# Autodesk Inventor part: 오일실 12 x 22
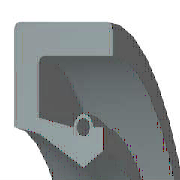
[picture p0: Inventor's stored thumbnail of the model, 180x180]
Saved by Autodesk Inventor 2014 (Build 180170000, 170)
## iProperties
IsCustomPart: 0
Created: 2015-10
Part Number: 오일실 12 x 22
Material: 고무
Description: 오일-실
Document SubType Name: Modeling
Standard: KS B 2804
Designer: mdu
Standards Organization: KS
Language: ko-KR
Size Designation: S - 12 22 7
Categories: <MemberInstance><Categories><Category DisplayName="샤프트 부품" InternalName="7f7aeb1f-a693-4053-b835-cee3144e0d98" Mnemonic="SHFT"><Category DisplayName="실링" Intern
Density: 0.93 g/cm^3
Appearance: 고무 - 검은색 - 버전 1.1
Author: mdu
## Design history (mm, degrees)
revolve "본체" stored, may be unused: angle "d17" = 90 deg
revolve "스프링1" stored, may be unused: angle "d18" = 90 deg
body "Solid1"
sketch "스케치1"
  geometry: L1 (0, 11)-(7, 11); L2 (7, 11)-(7, 9.75); L3 (7, 9.75)-(1.75, 9.75); L4 (0, 11)-(0, 8.1); L5 (0, 8.1)-(1.75, 7.75); L6 (1.75, 7.75)-(4.9, 6); L7 (4.9, 6)-(0, 6); L8 (6.3, 6.875)-(6.3, 8.1); L9 (0, 0)-(9.586, 0) reference; L10 (4.9, 6)-(6.3, 6.875); L11 (0, 18)-(0, -3) reference; L12 (-1.917, 0)-(11.503, 0) reference; L13 (4.2, 8.1)-(1.75, 8.59); L14 (1.75, 8.59)-(1.75, 9.75); L15 (6.3, 8.1)-(5.6, 8.1); C1 r 0.455 at (4.9, 8.1); A1 r 0.7 centre (4.9, 8.1) between (5.6, 8.1) and (4.2, 8.1)
  constraints: 26 end point, 5 horizontal alignment, 4 perpendicular, 2 centre point, 2 collinear, 2 horizontal, 2 parallel, 2 point on circle, 2 point on line, 2 vertical alignment, 1 coincident
  dimensions: "d0" = 22 diameter of L1 L9 (= SD2); "d1" = 13.75 diameter of L8.start L9 (= ABDM); "d2" = 1.25 distance of L1.end L2.end (computed from SD); "d3" = 0.91 diameter of C1 (= SPDI); "d4" = 1.4 diameter of A1 (= SPDA); "d5" = 12 diameter of L6.end L9 (= NND); "d6" = 15.5 diameter of L5.end L9 (= TKDM); "d7" = 16.2 diameter of L4.end L9 (= HLDM); "d8" = 4.9 distance from line of C1.centre L4 (= SPDST); "d9" = 6.3 distance between parallel lines of L8 L4 (= SDI); "d10" = 7 distance between parallel lines of L2 L4 (= SWDT); "d12" = 1.75 distance between parallel lines of L14 L4 (= SD)
fillet "모깎기1" dims "d11" = 0.3 (= RR)
other parameters: "SD2" = 22 [user parameter; used in 1 equation term], "SWDT" = 7 [user parameter; used in 1 equation term], "RR" = 0.3 [user parameter; used in 1 equation term], "SD" = 1.75 [user parameter; used in 2 equation terms], "NND" = 12 [user parameter; used in 1 equation term], "SPDA" = 1.4 [user parameter; used in 1 equation term], "SPDI" = 0.91 [user parameter; used in 1 equation term], "TKDM" = 15.5 [user parameter; used in 1 equation term], "HLDM" = 16.2 [user parameter; used in 1 equation term], "ABDM" = 13.75 [user parameter; used in 1 equation term], "SDI" = 6.3 [user parameter; used in 1 equation term], "SPDST" = 4.9 [user parameter; used in 1 equation term], "d13" = 0, "d14" = 0, "d15" = 0, "LAB" = 0.35 [user parameter]
